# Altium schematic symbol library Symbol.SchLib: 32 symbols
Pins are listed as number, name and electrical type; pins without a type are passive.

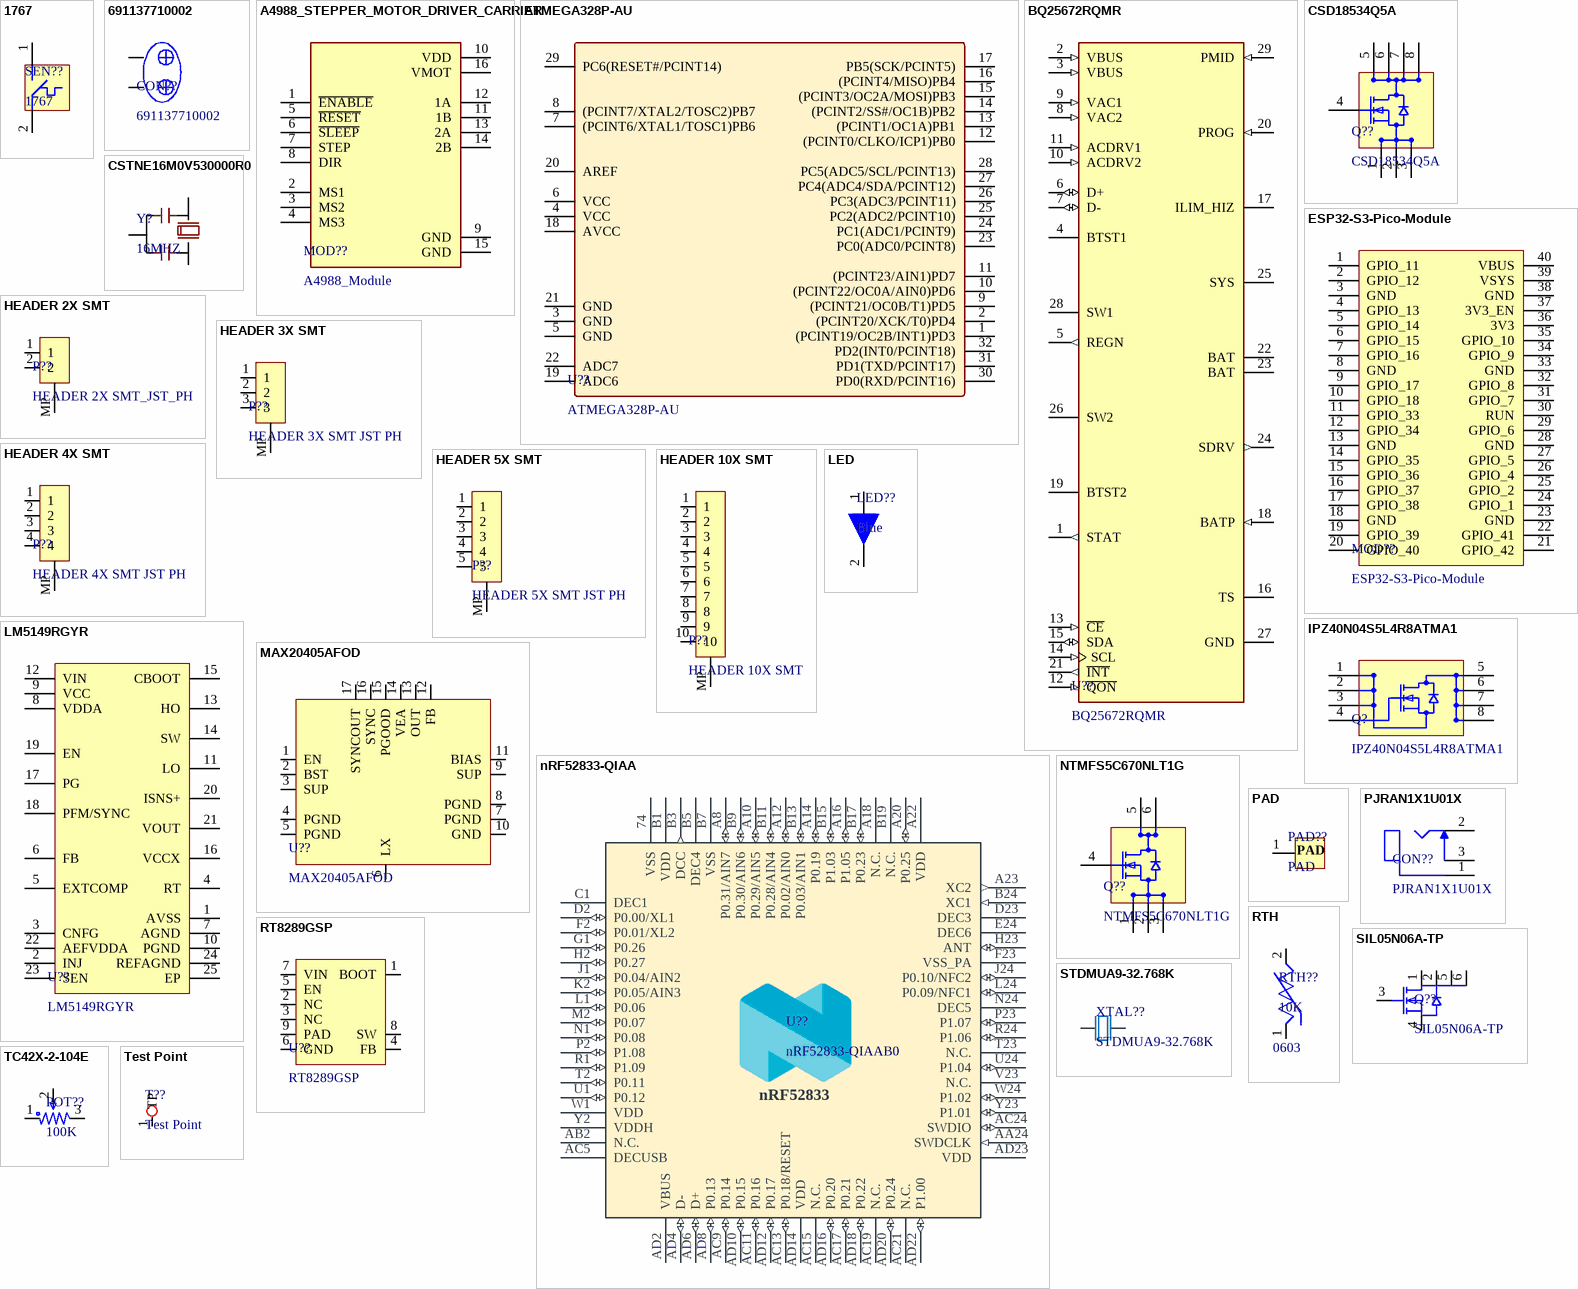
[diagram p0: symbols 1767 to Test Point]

## 1767
designator SEN??
footprint VIB_SENSOR_1767_D_5MM
pins: 1, 2

## 691137710002
designator CON??
2 Position Wire to Board Terminal Block Horizontal with Board 0.197" (5.00mm) Through Hole
pins: 1, 2

## A4988_STEPPER_MOTOR_DRIVER_CARRIER
designator MOD??, comment A4988_Module
footprint A4988_Stepper_Motor_Module
pins: 1 ~{ENABLE}, 2 MS1, 3 MS2, 4 MS3, 5 ~{RESET}, 6 ~{SLEEP}, 7 STEP, 8 DIR, 9 GND, 10 VDD, 11 1B, 12 1A, 13 2A, 14 2B, 15 GND, 16 VMOT

## ATMEGA328P-AU
designator U??
pins: 1 (PCINT19/OC2B/INT1)PD3, 2 (PCINT20/XCK/T0)PD4, 3 GND, 4 VCC, 5 GND, 6 VCC, 7 (PCINT6/XTAL1/TOSC1)PB6, 8 (PCINT7/XTAL2/TOSC2)PB7, 9 (PCINT21/OC0B/T1)PD5, 10 (PCINT22/OC0A/AIN0)PD6, 11 (PCINT23/AIN1)PD7, 12 (PCINT0/CLKO/ICP1)PB0, 13 (PCINT1/OC1A)PB1, 14 (PCINT2/SS#/OC1B)PB2, 15 (PCINT3/OC2A/MOSI)PB3, 16 (PCINT4/MISO)PB4, 17 PB5(SCK/PCINT5), 18 AVCC, 19 ADC6, 20 AREF, 21 GND, 22 ADC7, 23 PC0(ADC0/PCINT8), 24 PC1(ADC1/PCINT9), 25 PC2(ADC2/PCINT10), 26 PC3(ADC3/PCINT11), 27 PC4(ADC4/SDA/PCINT12), 28 PC5(ADC5/SCL/PCINT13), 29 PC6(RESET#/PCINT14), 30 PD0(RXD/PCINT16), 31 PD1(TXD/PCINT17), 32 PD2(INT0/PCINT18)

## BQ25672RQMR
designator U??
footprint VQFN-29_4MMx4MM
pins: 1 STAT (out), 2 VBUS (in), 3 VBUS (in), 4 BTST1, 5 REGN (out), 6 D+ (io), 7 D- (io), 8 VAC2 (in), 9 VAC1 (in), 10 ACDRV2 (in), 11 ACDRV1 (in), 12 ~{QON} (in), 13 ~{CE} (in), 14 SCL (in), 15 SDA (io), 16 TS, 17 ILIM_HIZ, 18 BATP (in), 19 BTST2, 20 PROG (in), 21 ~{INT} (out), 22 BAT (power), 23 BAT (power), 24 SDRV (out), 25 SYS (power), 26 SW2, 27 GND (power), 28 SW1, 29 PMID (in)

## CSD18534Q5A
designator Q??
footprint VSONP-8_5MMx6MM
pins: 1 S_1, 2 S_2, 3 S_3, 4 G, 5 D_1, 6 D_2, 7 D_3, 8 D_4

## CSTNE16M0V530000R0
designator Y?, comment 16MHZ
pins: 1 OSC1, 2 GND, 3 OSC2

## ESP32-S3-Pico-Module
designator MOD??
footprint ESP32-S3-PICO_Module
pins: 1 GPIO_11, 2 GPIO_12, 3 GND, 4 GPIO_13, 5 GPIO_14, 6 GPIO_15, 7 GPIO_16, 8 GND, 9 GPIO_17, 10 GPIO_18, 11 GPIO_33, 12 GPIO_34, 13 GND, 14 GPIO_35, 15 GPIO_36, 16 GPIO_37, 17 GPIO_38, 18 GND, 19 GPIO_39, 20 GPIO_40, 21 GPIO_42, 22 GPIO_41, 23 GND, 24 GPIO_1, 25 GPIO_2, 26 GPIO_4, 27 GPIO_5, 28 GND, 29 GPIO_6, 30 RUN, 31 GPIO_7, 32 GPIO_8, 33 GND, 34 GPIO_9, 35 GPIO_10, 36 3V3, 37 3V3_EN, 38 GND, 39 VSYS, 40 VBUS

## HEADER 2X SMT
designator P??, comment HEADER 2X SMT_JST_PH
footprint CONN_Header_SMD_Vertical_2P_2MM_B2B-PH-SM4-TB
pins: 1, 2, MP

## HEADER 3X SMT
designator P??, comment HEADER 3X SMT JST PH
footprint CONN_Header_SMD_Vertical_3P_2MM_B3B-PH-SM4-TB
pins: 1, 2, 3, MP

## HEADER 4X SMT
designator P??, comment HEADER 4X SMT JST PH
footprint CONN_Header_SMD_Vertical_4P_2MM_B4B-PH-SM4-TB
pins: 1, 2, 3, 4, MP

## HEADER 5X SMT
designator P??, comment HEADER 5X SMT JST PH
footprint CONN_Header_SMD_Vertical_5P_2MM_B5B-PH-SM4-TB
pins: 1, 2, 3, 4, 5, MP

## HEADER 10X SMT
designator P??
Dgikey Part Number: 455-B10B-PH-SM4-TBCT-ND
footprint CONN_Header_SMD_Vertical_10P_2MM_B10B-PH-SM4-TB (Footprint not found)
pins: 1, 2, 3, 4, 5, 6, 7, 8, 9, 10, MP

## IPZ40N04S5L4R8ATMA1
designator Q?
footprint PG-TSDSON-8
pins: 1 S_1, 2 S_2, 3 S_3, 4 G, 5 D_1, 6 D_2, 7 D_3, 8 D_4

## LED
designator LED??, comment Blue
footprint LED_SMD_0603_Blue
pins: 1 A, 2 C

## LM5149RGYR
designator U??
footprint VQFN-24_3.5MMx5.5MM
pins: 1 AVSS, 2 INJ, 3 CNFG, 4 RT, 5 EXTCOMP, 6 FB, 7 AGND, 8 VDDA, 9 VCC, 10 PGND, 11 LO, 12 VIN, 13 HO, 14 SW, 15 CBOOT, 16 VCCX, 17 PG, 18 PFM/SYNC, 19 EN, 20 ISNS+, 21 VOUT, 22 AEFVDDA, 23 SEN, 24 REFAGND, 25 EP

## MAX20405AFOD
designator U??
Buck Switching Regulator IC Positive Programmable (Fixed) 0.8V (3.3V) 1 Output 5A 17-PowerWFQFN
pins: 1 EN, 2 BST, 3 SUP, 4 PGND, 5 PGND, 6 LX, 7 PGND, 8 PGND, 9 SUP, 10 GND, 11 BIAS, 12 FB, 13 OUT, 14 VEA, 15 PGOOD, 16 SYNC, 17 SYNCOUT

## nRF52833-QIAA
designator U??, comment nRF52833-QIAAB0
footprint QFN-73_7MMx7MM
pins: 74 VSS (power), A8 P0.31/AIN7 (io), A10 P0.29/AIN5 (io), A12 P0.02/AIN0 (io), A14 P0.19 (io), A16 P1.05 (io), A18 N.C., A20 P0.25 (io), A22 VDD (power), A23 XC2 (out), AA24 SWDCLK (in), AB2 N.C., AC5 DECUSB (power), AC9 P0.14 (io), AC11 P0.16 (io), AC13 P0.18/RESET (io), AC15 N.C., AC17 P0.21 (io), AC19 N.C., AC21 N.C., AC24 SWDIO (io), AD2 VBUS (power), AD4 D- (io), AD6 D+ (io), AD8 P0.13 (io), AD10 P0.15 (io), AD12 P0.17 (io), AD14 VDD (power), AD16 P0.20 (io), AD18 P0.22 (io), AD20 P0.24 (io), AD22 P1.00 (io), AD23 VDD (power), B1 VDD (power), B3 DCC (out), B5 DEC4 (power), B7 VSS (power), B9 P0.30/AIN6 (io), B11 P0.28/AIN4 (io), B13 P0.03/AIN1 (io), B15 P1.03 (io), B17 P0.23 (io), B19 N.C., B24 XC1 (in), C1 DEC1 (power), D2 P0.00/XL1 (io), D23 DEC3 (power), E24 DEC6 (power), F2 P0.01/XL2 (io), F23 VSS_PA (power), G1 P0.26 (io), H2 P0.27 (io), H23 ANT (io), J1 P0.04/AIN2 (io), J24 P0.10/NFC2 (io), K2 P0.05/AIN3 (io), L1 P0.06 (io), L24 P0.09/NFC1 (io), M2 P0.07 (io), N1 P0.08 (io), N24 DEC5 (power), P2 P1.08 (io), P23 P1.07 (io), R1 P1.09 (io), R24 P1.06 (io), T2 P0.11 (io), T23 N.C., U1 P0.12 (io), U24 P1.04 (io), V23 N.C., W1 VDD (power), W24 P1.02 (io), Y2 VDDH (power), Y23 P1.01 (io)

## NTMFS5C670NLT1G
designator Q??
footprint DFN-5_5MMx6MM
pins: 1 S_1, 2 S_2, 3 S_3, 4 G, 5 D_1, 6 D_2

## PAD
designator PAD??
footprint PAD_SMD_0.8MMX0.9MM
pins: 1

## PJRAN1X1U01X
designator CON??
3.20mm ID, 9.00mm OD (RCA) Phono (RCA) Jack Mono Connector Solder
pins: 1, 2, 3

## RT8289GSP
designator U??
Buck Switching Regulator IC Positive Adjustable 1.222V 1 Output 5A 8-SOIC (0.154", 3.90mm Width) Exposed Pad
pins: 1 BOOT, 2 NC, 3 NC, 4 FB, 5 EN, 6 GND, 7 VIN, 8 SW, 9 PAD

## RTH
designator RTH??, comment 10K  Package: 0603
footprint RES_NTC_SMD_0603
pins: 1, 2

## SIL05N06A-TP
designator Q??
footprint SOT-23-6
pins: 1 D, 2 D, 3 G, 4 S, 5 D, 6 D

## STDMUA9-32.768K
designator XTAL??
footprint XTAL_3.20mmX1.50mm
pins: 1 inp, 2 out

## TC42X-2-104E
designator POT??, comment 100K
pins: 1, 2, 3

## Test Point
designator T??
footprint Test_Point_ROUND_1.5D
pins: 1 TP

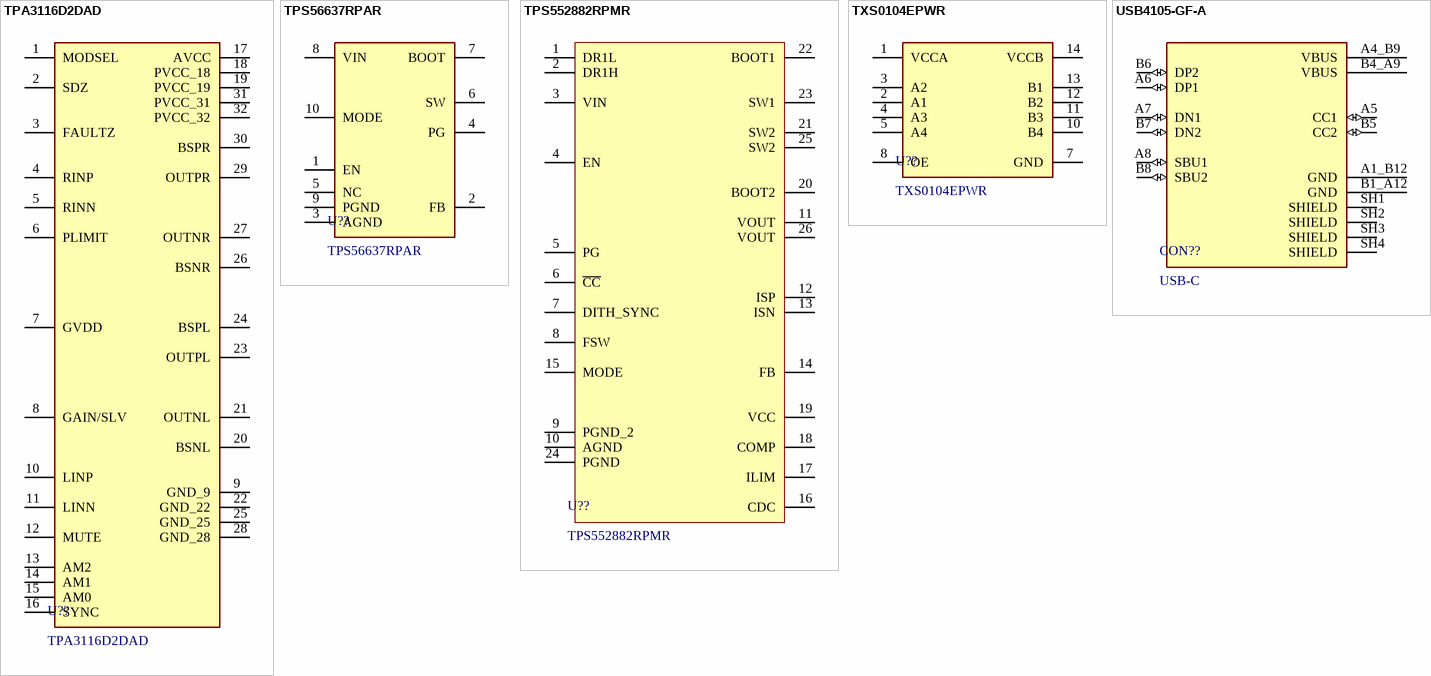
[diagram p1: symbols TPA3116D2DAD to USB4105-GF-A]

## TPA3116D2DAD
designator U??
Amplifier IC 2-Channel (Stereo) Class D 32-HTSSOP
pins: 1 MODSEL, 2 SDZ, 3 FAULTZ, 4 RINP, 5 RINN, 6 PLIMIT, 7 GVDD, 8 GAIN/SLV, 9 GND_9, 10 LINP, 11 LINN, 12 MUTE, 13 AM2, 14 AM1, 15 AM0, 16 SYNC, 17 AVCC, 18 PVCC_18, 19 PVCC_19, 20 BSNL, 21 OUTNL, 22 GND_22, 23 OUTPL, 24 BSPL, 25 GND_25, 26 BSNR, 27 OUTNR, 28 GND_28, 29 OUTPR, 30 BSPR, 31 PVCC_31, 32 PVCC_32

## TPS56637RPAR
designator U??
footprint VQFN-10-3MMx3MM
pins: 1 EN, 2 FB, 3 AGND, 4 PG, 5 NC, 6 SW, 7 BOOT, 8 VIN, 9 PGND, 10 MODE

## TPS552882RPMR
designator U??
footprint VQFN-26_4MMx3.5MM
pins: 1 DR1L, 2 DR1H, 3 VIN, 4 EN, 5 PG, 6 ~{CC}, 7 DITH_SYNC, 8 FSW, 9 PGND_2, 10 AGND, 11 VOUT, 12 ISP, 13 ISN, 14 FB, 15 MODE, 16 CDC, 17 ILIM, 18 COMP, 19 VCC, 20 BOOT2, 21 SW2, 22 BOOT1, 23 SW1, 24 PGND, 25 SW2, 26 VOUT

## TXS0104EPWR
designator U??
footprint TSSOP-14
pins: 1 VCCA, 2 A1, 3 A2, 4 A3, 5 A4, 7 GND, 8 OE, 10 B4, 11 B3, 12 B2, 13 B1, 14 VCCB

## USB4105-GF-A
designator CON??, comment USB-C
footprint CONN_USB-C_24PIN
pins: A1_B12 GND (power), A4_B9 VBUS (power), A5 CC1 (io), A6 DP1 (io), A7 DN1 (io), A8 SBU1 (io), B1_A12 GND (power), B4_A9 VBUS (power), B5 CC2 (io), B6 DP2 (io), B7 DN2 (io), B8 SBU2 (io), SH1 SHIELD (power), SH2 SHIELD (power), SH3 SHIELD (power), SH4 SHIELD (power)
